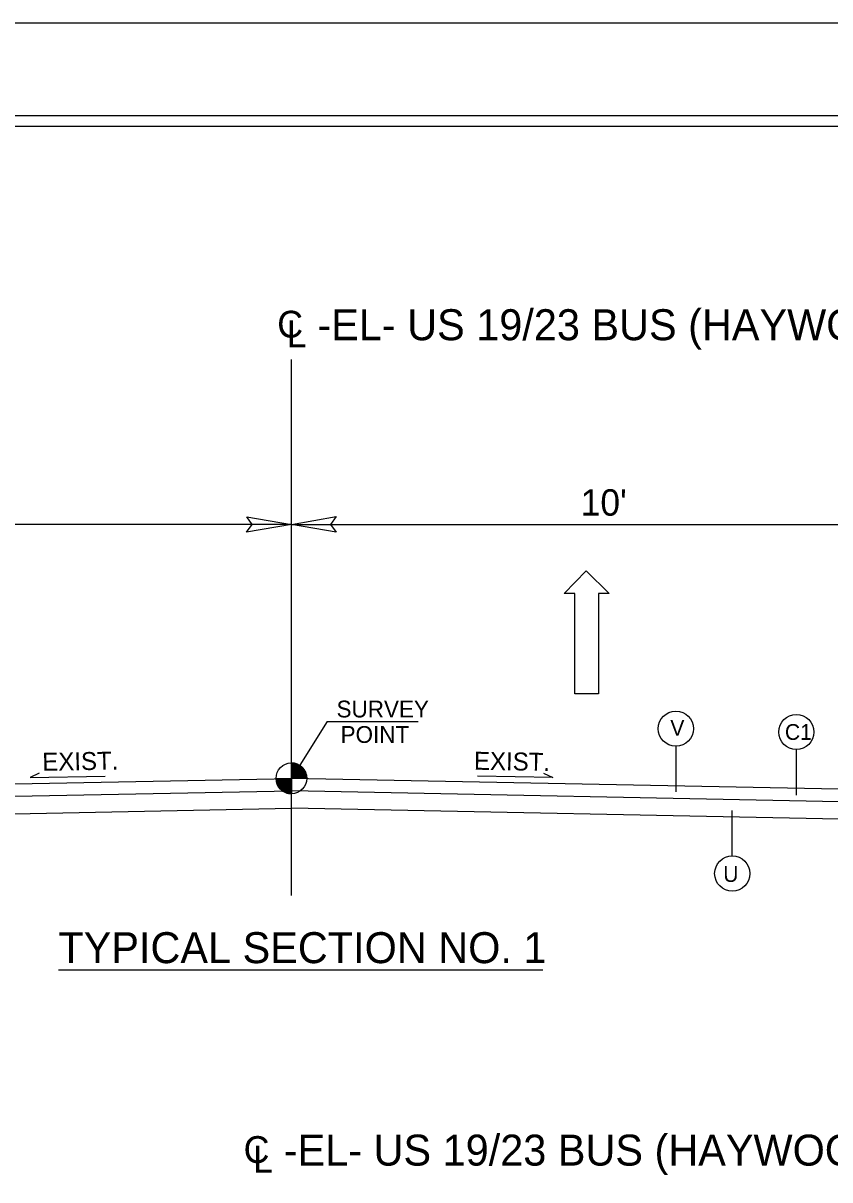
# Model space of a CAD drawing. Extents: x 1022283 to 1026986, y 174822 to 180471.
# Drawn here: x 1023665 to 1024154, y 179772 to 180471 of the extents above; entities that cross this region are included whole.
import ezdxf

# ---------------------------------------------------------------- set-up
doc = ezdxf.new("R2010")
doc.units = 0
for name, color, linetype in [('Default', 7, 'Continuous'), ('Prop Dimension', 7, 'Continuous'), ('Prop Lane Arrow CELL', 7, 'Continuous'), ('Prop Terminator CELL', 7, 'Continuous'), ('Sheet Cutting Line CELL', 7, 'Continuous'), ('Sheet Plot Border Inside CELL', 7, 'Continuous'), ('Sheet Plot Border Outside CELL', 7, 'Continuous'), ('Sheet Typical CELL', 7, 'Continuous'), ('Typical Berm Information CELL', 7, 'Continuous'), ('Typical Grade Point Symbol CELL', 7, 'Continuous'), ('Typical ID Circle CELL', 7, 'Continuous'), ('Typical Text Centerline CELL', 7, 'Continuous'), ('Typical Text Grade Point CELL', 7, 'Continuous'), ('Typical Text ID Circle CELL', 7, 'Continuous'), ('Typical Text Label CELL', 7, 'Continuous')]:
    doc.layers.add(name, color=color, linetype=linetype)

# ---------------------------------------------------------------- blocks, each defined once
blk = doc.blocks.new('Lane Arrow Through')
at = {"layer": 'Prop Lane Arrow CELL'}
for p, q in [((-3.15, 1.6), (-3.15, 3.1)), ((-3.15, 3.1), (0, 0)), ((-17.15, 1.6), (-3.15, 1.6)), ((-17.15, -1.7), (-17.15, 1.6)), ((0, 0), (-3.15, -3.2)), ((-3.15, -1.7), (-17.15, -1.7)), ((-3.15, -3.2), (-3.15, -1.7))]:
    blk.add_line(p, q, dxfattribs=at)

msp = doc.modelspace()

# ---------------------------------------------------------------- linework, layer by layer
at = {"layer": 'Default'}
for q in [(1023320.14, 180168.23), (1023320.14, 180168.23), (1024335.56, 180168.23), (1024335.56, 180168.23)]:
    msp.add_line((1023827.85, 180168.23), q, dxfattribs=at)
at = {"layer": 'Prop Dimension'}
for p, q in [((1023827.85, 180208.59), (1023827.85, 180268.04)), ((1023827.85, 179943.79), (1023827.85, 180208.59)), ((1023849.5, 180049.02), (1023827.85, 180014.58)), ((1023849.5, 180049.02), (1023827.85, 180014.58)), ((1023320.14, 180004.43), (1023827.85, 180014.58)), ((1023320.14, 180004.43), (1023827.85, 180014.58)), ((1024335.56, 180004.43), (1023827.85, 180014.58)), ((1024335.56, 180004.43), (1023827.85, 180014.58)), ((1023320.14, 179996.92), (1023827.85, 180007.08)), ((1023320.14, 179996.92), (1023827.85, 180007.08)), ((1024335.56, 179996.92), (1023827.85, 180007.08)), ((1024335.56, 179996.92), (1023827.85, 180007.08)), ((1023320.14, 179986.34), (1023827.85, 179996.5)), ((1024335.56, 179986.34), (1023827.85, 179996.5))]:
    msp.add_line(p, q, dxfattribs=at)
at = {"layer": 'Prop Terminator CELL'}
for points in [[(1023800.85, 180172.88), (1023827.85, 180168.23), (1023800.7, 180163.43), (1023804.15, 180168.23)], [(1023800.85, 180172.88), (1023827.85, 180168.23), (1023800.7, 180163.43), (1023804.15, 180168.23)], [(1023854.85, 180163.58), (1023827.85, 180168.23), (1023855, 180173.03), (1023851.55, 180168.23)], [(1023854.85, 180163.58), (1023827.85, 180168.23), (1023855, 180173.03), (1023851.55, 180168.23)]]:
    msp.add_lwpolyline(points, close=True, dxfattribs=at)
at = {"layer": 'Sheet Cutting Line CELL'}
msp.add_line((1026493.22, 180471.48), (1022283.22, 180471.48), dxfattribs=at)
at = {"layer": 'Sheet Plot Border Inside CELL'}
msp.add_lwpolyline([(1026481.97, 180415.35), (1022315.72, 180415.35), (1022315.72, 177777.6), (1026481.97, 177777.6)], close=True, dxfattribs=at)
at = {"layer": 'Sheet Plot Border Outside CELL'}
msp.add_lwpolyline([(1026493.22, 180471.48), (1022283.22, 180471.48), (1022283.22, 177721.48), (1026493.22, 177721.48)], close=True, dxfattribs=at)
at = {"layer": 'Sheet Typical CELL'}
msp.add_lwpolyline([(1026450.72, 180408.98), (1022700.72, 180408.98), (1022700.72, 177783.98), (1026450.72, 177783.98)], close=True, dxfattribs=at)
at = {"layer": 'Typical Berm Information CELL'}
for p, q in [((1023675.2, 180017.79), (1023669.68, 180015.03)), ((1023669.68, 180015.03), (1023715.19, 180015.94)), ((1023986.02, 180015.03), (1023940.51, 180015.94)), ((1023980.5, 180017.79), (1023986.02, 180015.03))]:
    msp.add_line(p, q, dxfattribs=at)
at = {"layer": 'Typical Grade Point Symbol CELL'}
for p, q in [((1023827.85, 180014.58), (1023827.85, 180023.88)), ((1023827.85, 180014.58), (1023827.85, 180023.88)), ((1023818.56, 180014.58), (1023827.85, 180014.58)), ((1023818.56, 180014.58), (1023827.85, 180014.58)), ((1023827.83, 180005.29), (1023827.85, 180014.58)), ((1023827.85, 180014.58), (1023827.83, 180005.29)), ((1023827.83, 180005.29), (1023827.85, 180014.58)), ((1023827.85, 180014.58), (1023827.83, 180005.29)), ((1023837.15, 180014.58), (1023827.85, 180014.58)), ((1023837.15, 180014.58), (1023827.85, 180014.58))]:
    msp.add_line(p, q, dxfattribs=at)
for points in [[(1023827.93, 180023.88), (1023827.93, 180023.88), (1023827.93, 180014.58)], [(1023827.93, 180023.88), (1023827.93, 180023.88), (1023827.93, 180014.58)], [(1023828.12, 180023.88), (1023828.12, 180014.58)], [(1023828.12, 180023.88), (1023828.12, 180014.58)], [(1023828.31, 180023.86), (1023828.31, 180014.58)], [(1023828.31, 180023.86), (1023828.31, 180014.58)], [(1023828.49, 180023.86), (1023828.49, 180014.58)], [(1023828.49, 180023.86), (1023828.49, 180014.58)], [(1023828.68, 180023.83), (1023828.68, 180014.58)], [(1023828.68, 180023.83), (1023828.68, 180014.58)], [(1023828.86, 180023.81), (1023828.86, 180014.58)], [(1023828.86, 180023.81), (1023828.86, 180014.58)], [(1023829.05, 180023.79), (1023829.05, 180014.58)], [(1023829.05, 180023.79), (1023829.05, 180014.58)], [(1023829.24, 180023.77), (1023829.24, 180014.58)], [(1023829.24, 180023.77), (1023829.24, 180014.58)], [(1023829.42, 180023.75), (1023829.42, 180014.58)], [(1023829.42, 180023.75), (1023829.42, 180014.58)], [(1023829.61, 180023.71), (1023829.61, 180014.58)], [(1023829.61, 180023.71), (1023829.61, 180014.58)], [(1023829.79, 180023.67), (1023829.79, 180014.58)], [(1023829.79, 180023.67), (1023829.79, 180014.58)], [(1023829.98, 180023.63), (1023829.98, 180014.58)], [(1023829.98, 180023.63), (1023829.98, 180014.58)], [(1023830.17, 180023.59), (1023830.17, 180014.58)], [(1023830.17, 180023.59), (1023830.17, 180014.58)], [(1023830.35, 180023.53), (1023830.35, 180014.58)], [(1023830.35, 180023.53), (1023830.35, 180014.58)], [(1023830.54, 180023.48), (1023830.54, 180014.58)], [(1023830.54, 180023.48), (1023830.54, 180014.58)], [(1023830.72, 180023.42), (1023830.72, 180014.58)], [(1023830.72, 180023.42), (1023830.72, 180014.58)], [(1023830.91, 180023.36), (1023830.91, 180014.58)], [(1023830.91, 180023.36), (1023830.91, 180014.58)], [(1023831.09, 180023.3), (1023831.09, 180014.58)], [(1023831.09, 180023.3), (1023831.09, 180014.58)], [(1023831.28, 180023.21), (1023831.28, 180014.58)], [(1023831.28, 180023.21), (1023831.28, 180014.58)], [(1023831.47, 180023.13), (1023831.47, 180014.58)], [(1023831.47, 180023.13), (1023831.47, 180014.58)], [(1023831.65, 180023.05), (1023831.65, 180014.58)], [(1023831.65, 180023.05), (1023831.65, 180014.58)], [(1023831.84, 180022.97), (1023831.84, 180014.58)], [(1023831.84, 180022.97), (1023831.84, 180014.58)], [(1023832.02, 180022.89), (1023832.02, 180014.58)], [(1023832.02, 180022.89), (1023832.02, 180014.58)], [(1023832.21, 180022.78), (1023832.21, 180014.58)], [(1023832.21, 180022.78), (1023832.21, 180014.58)], [(1023832.4, 180022.68), (1023832.4, 180014.58)], [(1023832.4, 180022.68), (1023832.4, 180014.58)], [(1023832.58, 180022.57), (1023832.58, 180014.58)], [(1023832.58, 180022.57), (1023832.58, 180014.58)], [(1023832.77, 180022.47), (1023832.77, 180014.58)], [(1023832.77, 180022.47), (1023832.77, 180014.58)], [(1023832.95, 180022.35), (1023832.95, 180014.58)], [(1023832.95, 180022.35), (1023832.95, 180014.58)], [(1023833.14, 180022.22), (1023833.14, 180014.58)], [(1023833.14, 180022.22), (1023833.14, 180014.58)], [(1023833.33, 180022.08), (1023833.33, 180014.58)], [(1023833.33, 180022.08), (1023833.33, 180014.58)], [(1023833.51, 180021.96), (1023833.51, 180014.58)], [(1023833.51, 180021.96), (1023833.51, 180014.58)], [(1023833.7, 180021.81), (1023833.7, 180014.58)], [(1023833.7, 180021.81), (1023833.7, 180014.58)], [(1023833.88, 180021.65), (1023833.88, 180014.58)], [(1023833.88, 180021.65), (1023833.88, 180014.58)], [(1023834.07, 180021.48), (1023834.07, 180014.58)], [(1023834.07, 180021.48), (1023834.07, 180014.58)], [(1023834.25, 180021.31), (1023834.25, 180014.58)], [(1023834.25, 180021.31), (1023834.25, 180014.58)], [(1023834.44, 180021.13), (1023834.44, 180014.58)], [(1023834.44, 180021.13), (1023834.44, 180014.58)], [(1023834.63, 180020.94), (1023834.63, 180014.58)], [(1023834.63, 180020.94), (1023834.63, 180014.58)], [(1023834.81, 180020.74), (1023834.81, 180014.58)], [(1023834.81, 180020.74), (1023834.81, 180014.58)], [(1023835, 180020.51), (1023835, 180014.58)], [(1023835, 180020.51), (1023835, 180014.58)], [(1023835.18, 180020.28), (1023835.18, 180014.58)], [(1023835.18, 180020.28), (1023835.18, 180014.58)], [(1023835.37, 180020.03), (1023835.37, 180014.58)], [(1023835.37, 180020.03), (1023835.37, 180014.58)], [(1023835.56, 180019.77), (1023835.56, 180014.58)], [(1023835.56, 180019.77), (1023835.56, 180014.58)], [(1023835.74, 180019.48), (1023835.74, 180014.58)], [(1023835.74, 180019.48), (1023835.74, 180014.58)], [(1023835.93, 180019.17), (1023835.93, 180014.58)], [(1023835.93, 180019.17), (1023835.93, 180014.58)], [(1023836.11, 180018.84), (1023836.11, 180014.58)], [(1023836.11, 180018.84), (1023836.11, 180014.58)], [(1023836.3, 180018.44), (1023836.3, 180014.58)], [(1023836.3, 180018.44), (1023836.3, 180014.58)], [(1023836.49, 180018.01), (1023836.49, 180014.58)], [(1023836.49, 180018.01), (1023836.49, 180014.58)], [(1023836.67, 180017.49), (1023836.67, 180014.58)], [(1023836.67, 180017.49), (1023836.67, 180014.58)], [(1023836.86, 180016.85), (1023836.86, 180014.58)], [(1023836.86, 180016.85), (1023836.86, 180014.58)], [(1023837.04, 180015.9), (1023837.04, 180014.58)], [(1023837.04, 180015.9), (1023837.04, 180014.58)], [(1023818.6, 180014.58), (1023818.6, 180013.57)], [(1023818.6, 180014.58), (1023818.6, 180013.57)], [(1023818.78, 180014.58), (1023818.78, 180012.47)], [(1023818.78, 180014.58), (1023818.78, 180012.47)], [(1023818.97, 180014.58), (1023818.97, 180011.81)], [(1023818.97, 180014.58), (1023818.97, 180011.81)], [(1023819.16, 180014.58), (1023819.16, 180011.25)], [(1023819.16, 180014.58), (1023819.16, 180011.25)], [(1023819.34, 180014.58), (1023819.34, 180010.82)], [(1023819.34, 180014.58), (1023819.34, 180010.82)], [(1023819.53, 180014.58), (1023819.53, 180010.43)], [(1023819.53, 180014.58), (1023819.53, 180010.43)], [(1023819.71, 180014.58), (1023819.71, 180010.08)], [(1023819.71, 180014.58), (1023819.71, 180010.08)], [(1023819.9, 180014.58), (1023819.9, 180009.75)], [(1023819.9, 180014.58), (1023819.9, 180009.75)], [(1023820.09, 180014.58), (1023820.09, 180009.46)], [(1023820.09, 180014.58), (1023820.09, 180009.46)], [(1023820.27, 180014.58), (1023820.27, 180009.19)], [(1023820.27, 180014.58), (1023820.27, 180009.19)], [(1023820.46, 180014.58), (1023820.46, 180008.94)], [(1023820.46, 180014.58), (1023820.46, 180008.94)], [(1023820.64, 180014.58), (1023820.64, 180008.71)], [(1023820.64, 180014.58), (1023820.64, 180008.71)], [(1023820.83, 180014.58), (1023820.83, 180008.49)], [(1023820.83, 180014.58), (1023820.83, 180008.49)], [(1023821.01, 180014.58), (1023821.01, 180008.28)], [(1023821.01, 180014.58), (1023821.01, 180008.28)], [(1023821.2, 180014.58), (1023821.2, 180008.07)], [(1023821.2, 180014.58), (1023821.2, 180008.07)], [(1023821.39, 180014.58), (1023821.39, 180007.89)], [(1023821.39, 180014.58), (1023821.39, 180007.89)], [(1023821.57, 180014.58), (1023821.57, 180007.72)], [(1023821.57, 180014.58), (1023821.57, 180007.72)], [(1023821.76, 180014.58), (1023821.76, 180007.56)], [(1023821.76, 180014.58), (1023821.76, 180007.56)], [(1023821.94, 180014.58), (1023821.94, 180007.39)], [(1023821.94, 180014.58), (1023821.94, 180007.39)], [(1023822.13, 180014.58), (1023822.13, 180007.25)], [(1023822.13, 180014.58), (1023822.13, 180007.25)], [(1023822.32, 180014.58), (1023822.32, 180007.1)], [(1023822.32, 180014.58), (1023822.32, 180007.1)], [(1023822.5, 180014.58), (1023822.5, 180006.98)], [(1023822.5, 180014.58), (1023822.5, 180006.98)], [(1023822.69, 180014.58), (1023822.69, 180006.86)], [(1023822.69, 180014.58), (1023822.69, 180006.86)], [(1023822.87, 180014.58), (1023822.87, 180006.73)], [(1023822.87, 180014.58), (1023822.87, 180006.73)], [(1023823.06, 180014.58), (1023823.06, 180006.61)], [(1023823.06, 180014.58), (1023823.06, 180006.61)], [(1023823.25, 180014.58), (1023823.25, 180006.5)], [(1023823.25, 180014.58), (1023823.25, 180006.5)], [(1023823.43, 180014.58), (1023823.43, 180006.4)], [(1023823.43, 180014.58), (1023823.43, 180006.4)], [(1023823.62, 180014.58), (1023823.62, 180006.3)], [(1023823.62, 180014.58), (1023823.62, 180006.3)], [(1023823.8, 180014.58), (1023823.8, 180006.22)], [(1023823.8, 180014.58), (1023823.8, 180006.22)], [(1023823.99, 180014.58), (1023823.99, 180006.13)], [(1023823.99, 180014.58), (1023823.99, 180006.13)], [(1023824.18, 180014.58), (1023824.18, 180006.05)], [(1023824.18, 180014.58), (1023824.18, 180006.05)], [(1023824.36, 180014.58), (1023824.36, 180005.97)], [(1023824.36, 180014.58), (1023824.36, 180005.97)], [(1023824.55, 180014.58), (1023824.55, 180005.88)], [(1023824.55, 180014.58), (1023824.55, 180005.88)], [(1023824.73, 180014.58), (1023824.73, 180005.82)], [(1023824.73, 180014.58), (1023824.73, 180005.82)], [(1023824.92, 180014.58), (1023824.92, 180005.76)], [(1023824.92, 180014.58), (1023824.92, 180005.76)], [(1023825.1, 180014.58), (1023825.1, 180005.7)], [(1023825.1, 180014.58), (1023825.1, 180005.7)], [(1023825.29, 180014.58), (1023825.29, 180005.66)], [(1023825.29, 180014.58), (1023825.29, 180005.66)], [(1023825.48, 180014.58), (1023825.48, 180005.6)], [(1023825.48, 180014.58), (1023825.48, 180005.6)], [(1023825.66, 180014.58), (1023825.66, 180005.55)], [(1023825.66, 180014.58), (1023825.66, 180005.55)], [(1023825.85, 180014.58), (1023825.85, 180005.51)], [(1023825.85, 180014.58), (1023825.85, 180005.51)], [(1023826.03, 180014.58), (1023826.03, 180005.47)], [(1023826.03, 180014.58), (1023826.03, 180005.47)], [(1023826.22, 180014.58), (1023826.22, 180005.43)], [(1023826.22, 180014.58), (1023826.22, 180005.43)], [(1023826.41, 180014.58), (1023826.41, 180005.41)], [(1023826.41, 180014.58), (1023826.41, 180005.41)], [(1023826.59, 180014.58), (1023826.59, 180005.37)], [(1023826.59, 180014.58), (1023826.59, 180005.37)], [(1023826.78, 180014.58), (1023826.78, 180005.35)], [(1023826.78, 180014.58), (1023826.78, 180005.35)], [(1023826.96, 180014.58), (1023826.96, 180005.33)], [(1023826.96, 180014.58), (1023826.96, 180005.33)], [(1023827.15, 180014.58), (1023827.15, 180005.31)], [(1023827.15, 180014.58), (1023827.15, 180005.31)], [(1023827.34, 180014.58), (1023827.34, 180005.31)], [(1023827.34, 180014.58), (1023827.34, 180005.31)], [(1023827.52, 180014.58), (1023827.52, 180005.29)], [(1023827.52, 180014.58), (1023827.52, 180005.29)], [(1023827.71, 180014.58), (1023827.71, 180005.29), (1023827.71, 180005.29)], [(1023827.71, 180014.58), (1023827.71, 180005.29), (1023827.71, 180005.29)]]:
    msp.add_lwpolyline(points, dxfattribs=at)
msp.add_circle((1023827.84, 180014.58), 9.3, dxfattribs=at)
msp.add_circle((1023827.84, 180014.58), 9.3, dxfattribs=at)
for start, end in [(359.99048, 89.99048), (359.99048, 89.99048), (179.99048, 269.99048), (179.99048, 269.99048)]:
    msp.add_arc((1023827.84, 180014.58), 9.3, start, end, dxfattribs=at)
at = {"layer": 'Typical ID Circle CELL'}
for p, q in [((1024060.49, 180033.98), (1024060.49, 180006.45)), ((1024133.38, 180031.97), (1024133.38, 180004.44)), ((1024094.62, 179967.65), (1024094.62, 179995.18))]:
    msp.add_line(p, q, dxfattribs=at)
for centre in [(1024060.49, 180044.62), (1024133.38, 180042.62), (1024094.62, 179957)]:
    msp.add_circle(centre, 10.65, dxfattribs=at)
at = {"layer": 'Typical Text Grade Point CELL'}
msp.add_line((1023849.5, 180049.02), (1023904.6, 180049.02), dxfattribs=at)
at = {"layer": 'Typical Text Label CELL'}
msp.add_line((1023686.83, 179898.78), (1023980.08, 179898.78), dxfattribs=at)

# ---------------------------------------------------------------- block references
at = {"layer": 'Prop Lane Arrow CELL', "xscale": 4.329849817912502, "yscale": 4.329849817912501, "rotation": 90.00000000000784}
msp.add_blockref('Lane Arrow Through', (1024006.3, 180140.04), dxfattribs=at)
msp.add_blockref('Lane Arrow Through', (1024006.3, 180140.04), dxfattribs=at)

# ---------------------------------------------------------------- texts
at = {"layer": 'Prop Dimension'}
for s, height, p in [('-EL- US 19/23 BUS (HAYWOOD RD) ', 18.75, (1023843.57, 180279.64)), ("10'", 16, (1024002.92, 180173.5)), ('-EL- US 19/23 BUS (HAYWOOD RD) ', 18.75, (1023823.22, 179780.3))]:
    msp.add_text(s, height=height, dxfattribs=at).set_placement(p)
at = {"layer": 'Typical Berm Information CELL'}
for rotation, p in [(0.99274, (1023677.17, 180019.13)), (359.00726, (1023938.25, 180019.83))]:
    msp.add_text('EXIST.', height=10.873, rotation=rotation, dxfattribs=at).set_placement(p)
at = {"layer": 'Typical Text Centerline CELL'}
for p in [(1023819.26, 180281.25), (1023798.92, 179781.91)]:
    msp.add_text('C', height=16.22, dxfattribs=at).set_placement(p)
for p in [(1023824.93, 180275.44), (1023804.58, 179776.1)]:
    msp.add_text('L', height=16.22, rotation=359.9469, dxfattribs=at).set_placement(p)
at = {"layer": 'Typical Text Grade Point CELL'}
for s, p in [('SURVEY', (1023855.17, 180051.45)), ('POINT', (1023857.61, 180036.05))]:
    msp.add_text(s, height=10.163, dxfattribs=at).set_placement(p)
at = {"layer": 'Typical Text ID Circle CELL'}
for s, height, p in [('V', 9.53, (1024057.15, 180040.32)), ('C1', 9.534, (1024126.5, 180037.88)), ('U', 9.53, (1024089.17, 179951.94))]:
    msp.add_text(s, height=height, dxfattribs=at).set_placement(p)
at = {"layer": 'Typical Text Label CELL'}
msp.add_text('TYPICAL SECTION NO. 1', height=18.75, dxfattribs=at).set_placement((1023686.83, 179902.78))

doc.saveas('drawing.dxf')
